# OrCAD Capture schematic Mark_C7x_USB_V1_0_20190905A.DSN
size A3; title: Mark_C7x_USB; rev: 1.0; note: USB_ETH
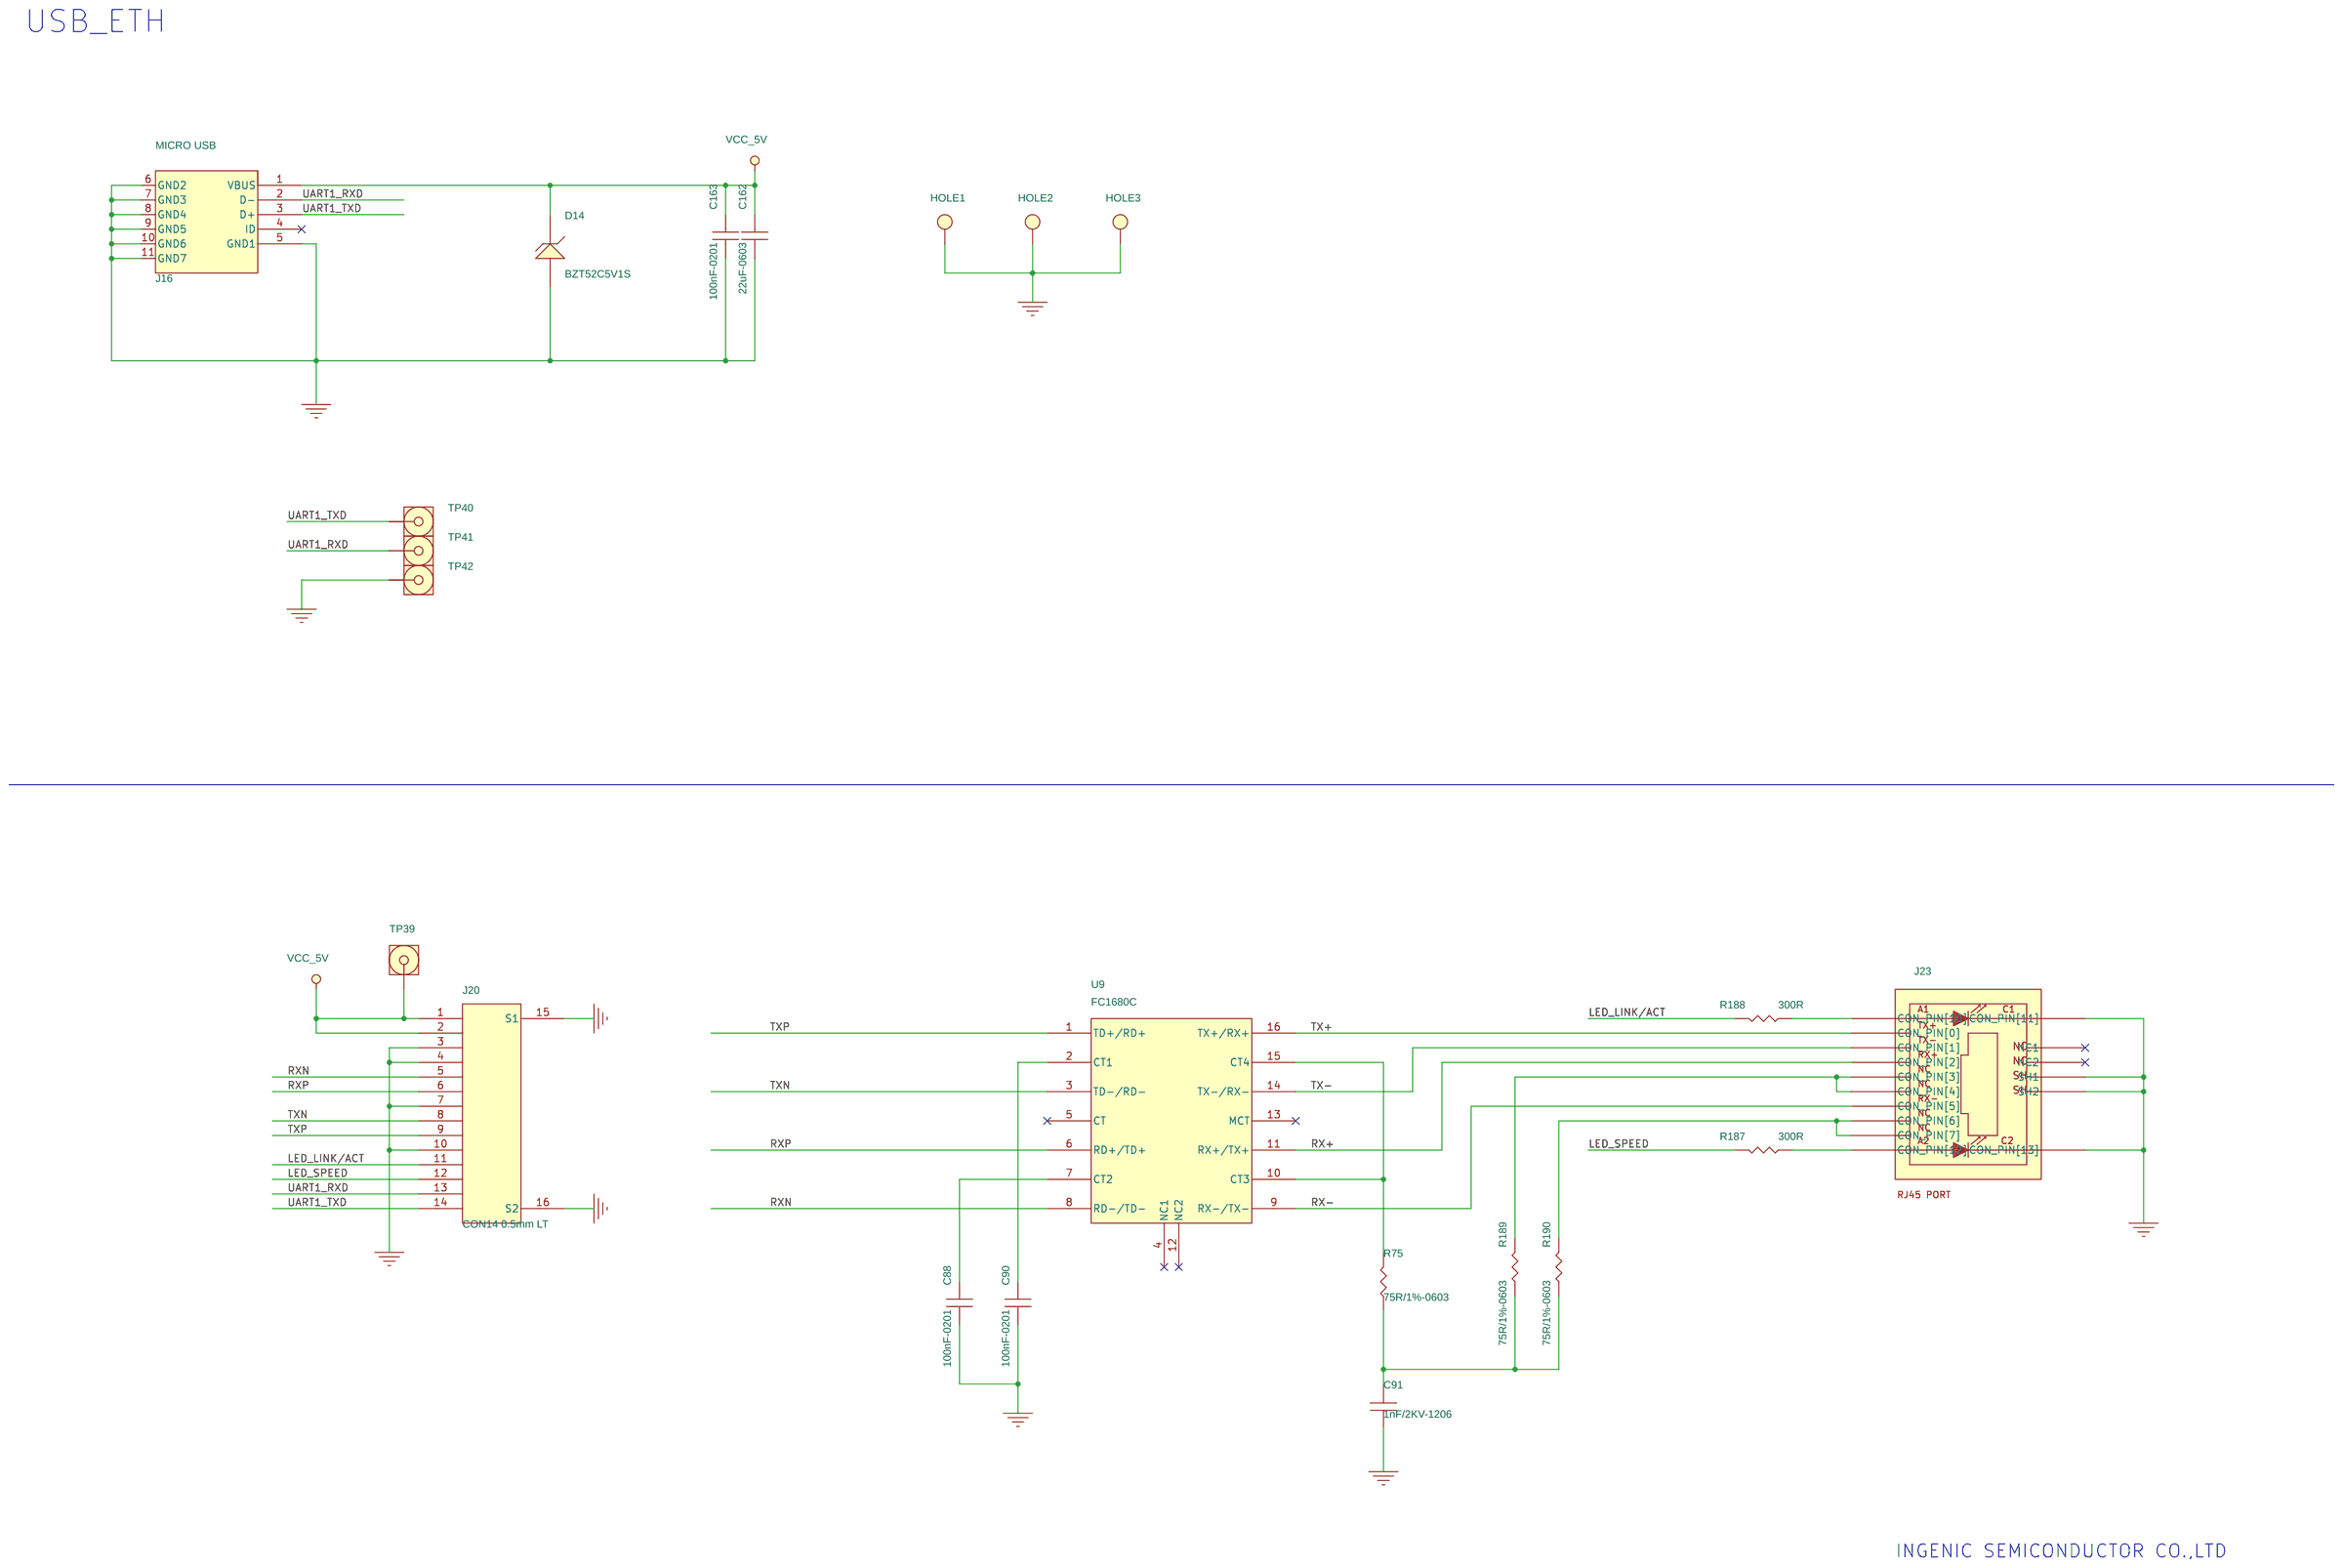
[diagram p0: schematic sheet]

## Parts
C88  100nF-0201  [C0201]
C90  100nF-0201  [C0201]
C91  1nF/2KV-1206  [C1206]
C162  22uF-0603  [C0603]
C163  100nF-0201  [C0201]
D14  BZT52C5V1S  [SOD323]
HOLE1  T POINT R  [H3D5MM_2D2MM]
HOLE2  T POINT R  [H3D5MM_2D2MM]
HOLE3  T POINT R  [H3D5MM_2D2MM]
J16  MICRO USB  [MICROUSB_B_USB0565]
J20  CON14 0.5mm LT  [FPC-CON14-0D5-LT]
J23  RJ45 With Led  [RJ45-LED-1A]
R75  75R/1%-0603  [R0603]
R187  300R  [R0402]
R188  300R  [R0402]
R189  75R/1%-0603  [R0603]
R190  75R/1%-0603  [R0603]
TP39  TP  [TEST_SMD]
TP40  TP  [TEST_SMD]
TP41  TP  [TEST_SMD]
TP42  TP  [TEST_SMD]
U9  FC1680C  [QFP16_1D27]

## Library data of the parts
C88 C90 C163 = CAP: Capacitor-100nF,+/-20%,X7R,25V-0201; Part Number: 02.0054.00; Part Type: 0201表贴普通电容; 供应商: Eyang / Murata; 规格型号1: C0201X7R104M250NTA; 联系人: 何俊 / 吴铭; 手机: 18317187178 / 13761466262; 邮箱: hejunxs@szeyang.com / cherry.wu@murata.com
C91 = CAP: Capacitor-1nF,+/-10%,X5R,2KV-1206; Part Number: 02.0030.00; Part Type: 1206表贴高压电容; 供应商: Eyang / Murata; 规格型号1: C1206X7R102K202NR0; 规格型号2: GR431BR7LA102KW66L; 联系人: 何俊 / 吴铭; 手机: 18317187178 / 13761466262; 邮箱: hejunxs@szeyang.com / cherry.wu@murata.com; Datasheet: GR431BR7LA102KW66-01_20150127.pdf
C162 = CAP: Capacitor-22uF,+/-20%,X5R,10V-0603; Part Number: 02.0039.00; Part Type: 0603表贴普通电容; 供应商: Eyang / Murata; 规格型号1: C0603X5R226M100NRW; 联系人: 何俊 / 吴铭; 手机: 18317187178 / 13761466262; 邮箱: hejunxs@szeyang.com / cherry.wu@murata.com
D14 = DIODE_WY: CHANGJIANG ELECTRONICS BZT52C5V1S  ZENER DIODE; Part Number: 09.0001.00; Part Type: 稳压二极管
HOLE1-HOLE3 = T_POINT_R
J16 = MICROUSB_0: USB Connector MICROUSB 5P 0.65mmpitch 前插后贴5.65无柱; Part Number: 04.0093.00; Part Type: USB连接器; 规格型号1: MICRO USB 5S B 型前插后贴5.65无柱; Datasheet: MICRO USB 5S B 型前插后贴5.65无柱 Model (1).pdf
J20 = FPCCON_7X2: HOLY 0.5mm pitch FPC LT 14 Pin Connector; Part Number: 04.0084.00; Part Type: 0.5mm立贴FPC连接器; 供应商: 深圳宏利电子; 规格型号1: FPC0.5mm-14P立贴正位; 联系人: 卢利国; 手机: 13670123195; 邮箱: 1026742818@qq.com; Datasheet: 0.5mm立式正位全包.pdf
J23 = RJ45_1X1_LED: RJ45-LED-1A Ethernet Connector With LED; Part Number: 10.0001.00; Part Type: 网口; 规格型号1: RJ45带灯; Datasheet: PCB-937带灯.pdf
R75 R189 R190 = RES: Resistor-75R,+/-1%,1/10W-0603; Part Number: 01.0052.00; Part Type: 0603表贴高精度电阻; 供应商: Eyang; 规格型号1: R0603RXX750XF10LTS; 联系人: 何俊; 手机: 18317187178; 邮箱: hejunxs@szeyang.com
R187 R188 = RES: Resistor-300R,+/-5%,1/16W-0402; Part Number: 01.0011.00; Part Type: 0402表贴普通电阻; 供应商: Eyang; 规格型号1: R0402RXX301XJ16LTA; 联系人: 何俊; 手机: 18317187178; 邮箱: hejunxs@szeyang.com
TP39-TP42 = TP: SMD Test Point φ1mm; Part Number: AA.0001.00; Part Type: Test Point
U9 = FC1680C: IC-FLY FC1680C 10/100 Small Package Transformer module; Part Number: 06.0010.00; Part Type: 网络变压器; 供应商: 上海飞芯电子; 联系人: 刘经纬; 手机: 18621560356; 邮箱: jack_liu@ic-fly.com; Datasheet: FC1680C.20120213.pdf

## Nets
GND: C88.2 C90.2 C91.1 C162.2 C163.2 D14.1 HOLE1.1(TP) HOLE2.1(TP) HOLE3.1(TP) J16.5(GND1) J16.6(GND2) J16.7(GND3) J16.8(GND4) J16.9(GND5) J16.10(GND6) J16.11(GND7) J20.3 J20.4 J20.7 J20.10 J20.15(S1) J20.16(S2) J23.9(SH1) J23.10(SH2) J23.12(CON_PIN[11]) J23.14(CON_PIN[13]) TP42.1
VCC_5V: C162.1 C163.1 D14.2 J16.1(VBUS) J20.1 J20.2 TP39.1
LED_LINK/ACT: J20.11 R188.2
LED_SPEED: J20.12 R187.2
RX+: J23.3(CON_PIN[2]) U9.11(RX+/TX+)
RX-: J23.6(CON_PIN[5]) U9.9(RX-/TX-)
RXN: J20.5 U9.8(RD-/TD-)
RXP: J20.6 U9.6(RD+/TD+)
TX+: J23.1(CON_PIN[0]) U9.16(TX+/RX+)
TX-: J23.2(CON_PIN[1]) U9.14(TX-/RX-)
TXN: J20.8 U9.3(TD-/RD-)
TXP: J20.9 U9.1(TD+/RD+)
UART1_RXD: J16.2(D-) J20.13 TP41.1
UART1_TXD: J16.3(D+) J20.14 TP40.1
N16349692: R75.2 U9.10(CT3) U9.15(CT4)
N16349716: C90.1 U9.2(CT1)
N16349770: C88.1 U9.7(CT2)
N16349838: C91.2 R75.1 R189.1 R190.1
N16352020: J23.4(CON_PIN[3]) J23.5(CON_PIN[4]) R189.2
N16352037: J23.7(CON_PIN[6]) J23.8(CON_PIN[7]) R190.2
N16360139: J23.11(CON_PIN[10]) R188.1
N16602826: J23.13(CON_PIN[12]) R187.1

Not connected (* = marked no-connect by the designer): J16 4(ID)*; J23 15(NC1)* 16(NC2)*; U9 4(NC1)* 5(CT)* 12(NC2)* 13(MCT)*

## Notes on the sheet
- USB_ETH
- INGENIC SEMICONDUCTOR CO.,LTD
